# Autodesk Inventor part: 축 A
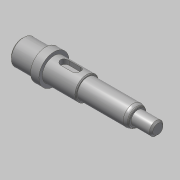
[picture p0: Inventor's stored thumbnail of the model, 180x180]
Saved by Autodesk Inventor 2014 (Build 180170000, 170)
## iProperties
Created: 2020-04
Part Number: 축 A
Material: 강철, 연강
Document SubType Name: Modeling
Designer: mduedu
Density: 7.86 g/cm^3
Appearance: Steel
Mass: 83.1664 g
Surface Area: 37.6212 cm^2
Volume: 10.581 cm^3
Author: mduedu
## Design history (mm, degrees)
sketch "스케치1"
  geometry: L1 (0, 0)-(14, 0); L2 (14, 0)-(14, 7.5); L3 (14, 7.5)-(0, 7.5); L4 (0, 7.5)-(0, 0); L5 (14, 0)-(19, 0); L6 (19, 0)-(19, 9); L7 (19, 9)-(14, 9); L8 (14, 9)-(14, 0); L9 (19, 0)-(39, 0); L10 (39, 0)-(39, 7); L11 (39, 7)-(19, 7); L12 (19, 7)-(19, 0); L13 (39, 0)-(69, 0); L14 (69, 0)-(69, 6); L15 (69, 6)-(39, 6); L16 (39, 6)-(39, 0); L17 (69, 0)-(81, 0); L18 (81, 0)-(81, 4); L19 (81, 4)-(69, 4); L20 (69, 4)-(69, 0)
  constraints: 40 end point, 10 parallel, 5 horizontal, 5 perpendicular
  dimensions: "d0" = 81 distance between parallel lines of L18 L4; "d2" = 14 distance of L2.end L3.end; "d3" = 5 distance of L6.end L7.end; "d4" = 12 distance of L18.end L19.end; "d5" = 8 diameter of L19 L17; "d6" = 12 diameter of L15 L13; "d7" = 14 diameter of L11 L9; "d8" = 15 diameter of L3 L1; "d9" = 18 diameter of L7 L5; "d10" = 42 distance between parallel lines of L10 L18
revolve "회전1" sketch "스케치1" stored, may be unused: angle "d11" = 90 deg
sketch "스케치2"
  geometry: L1 (0, -7.5)-(0, 7.5) reference; L2 (0, 7.5)-(14, 7.5) reference; L3 (14, 7.5)-(14, 9) reference; L4 (14, 9)-(19, 9) reference; L5 (19, 9)-(19, 7) reference; L6 (19, 7)-(39, 7) reference; L7 (39, 7)-(39, 6) reference; L8 (39, 6)-(69, 6) reference; L9 (69, 6)-(69, 4) reference; L10 (69, 4)-(81, 4) reference; L11 (81, 4)-(81, -4) reference; L12 (81, -4)-(69, -4) reference; L13 (69, -4)-(69, -6) reference; L14 (69, -6)-(39, -6) reference; L15 (39, -6)-(39, -7) reference; L16 (39, -7)-(19, -7) reference; L17 (19, -7)-(19, -9) reference; L18 (19, -9)-(14, -9) reference; L19 (14, -9)-(14, -7.5) reference; L20 (14, -7.5)-(0, -7.5) reference; L21 (81, -4)-(73, -4); L22 (73, -4)-(73, -2.8); L23 (73, -2.8)-(81, -2.8); L24 (81, -2.8)-(81, -4); 1 further point
  constraints: 8 end point, 2 parallel, 1 horizontal, 1 perpendicular
  dimensions: "d12" = 8 distance of L22.end L23.end; "d13" = 1.2 distance of L21.end L22.end
extrude "돌출1" cut sketch "스케치2" stored distance "d14" = 2; taper "d15" = 0 deg
fillet "모깎기1" dims "d16" = 1
sketch "스케치3"
  geometry: L1 (0, -7.5)-(0, 7.5) reference; L2 (0, 7.5)-(14, 7.5) reference; L3 (14, 7.5)-(14, 9) reference; L4 (14, 9)-(19, 9) reference; L5 (19, 9)-(19, 7) reference; L6 (19, 7)-(39, 7) reference; L7 (39, 7)-(39, 6) reference; L8 (39, 6)-(69, 6) reference; L9 (69, 6)-(69, 4) reference; L10 (69, 4)-(81, 4) reference; L11 (81, 4)-(81, -2.8) reference; L12 (81, -2.8)-(73, -2.8) reference; L13 (73, -2.8)-(73, -4) reference; L14 (73, -4)-(69, -4) reference; L15 (69, -4)-(69, -6) reference; L16 (69, -6)-(39, -6) reference; L17 (39, -6)-(39, -7) reference; L18 (39, -7)-(19, -7) reference; L19 (19, -7)-(19, -9) reference; L20 (19, -9)-(14, -9) reference; L21 (14, -9)-(14, -7.5) reference; L22 (14, -7.5)-(0, -7.5) reference; L23 (23, 7)-(35, 7); L24 (35, 7)-(35, 4); L25 (35, 4)-(23, 4); L26 (23, 4)-(23, 7); 1 further point
  constraints: 8 end point, 2 parallel, 1 horizontal, 1 perpendicular, 1 point on line
  dimensions: "d17" = 12 distance of L24.end L25.end; "d18" = 3 distance of L23.end L24.end; "d19" = 4 distance from line of L26 L4.end
extrude "돌출2" cut sketch "스케치3" stored distance "d20" = 5; taper "d21" = 0 deg
fillet "모깎기2" dims "d22" = 2.5
chamfer "모따기1" distance "d23" = 1; stored, may be unused: second distance "d24" = 2, angle "d25" = 45 deg
chamfer "모따기2" distance "d26" = 0.5; stored, may be unused: second distance "d27" = 2, angle "d28" = 45 deg
fillet "모깎기3" dims "d29" = 0.3
chamfer "모따기3" distance "d30" = 1.56; stored, may be unused: second distance "d31" = 2, angle "d32" = 30 deg
fillet "모깎기4" dims "d33" = 4, "d34" = 0.5
node "솔리드1"
node "절단 모서리 투영1"
node "절단 모서리 투영2"
